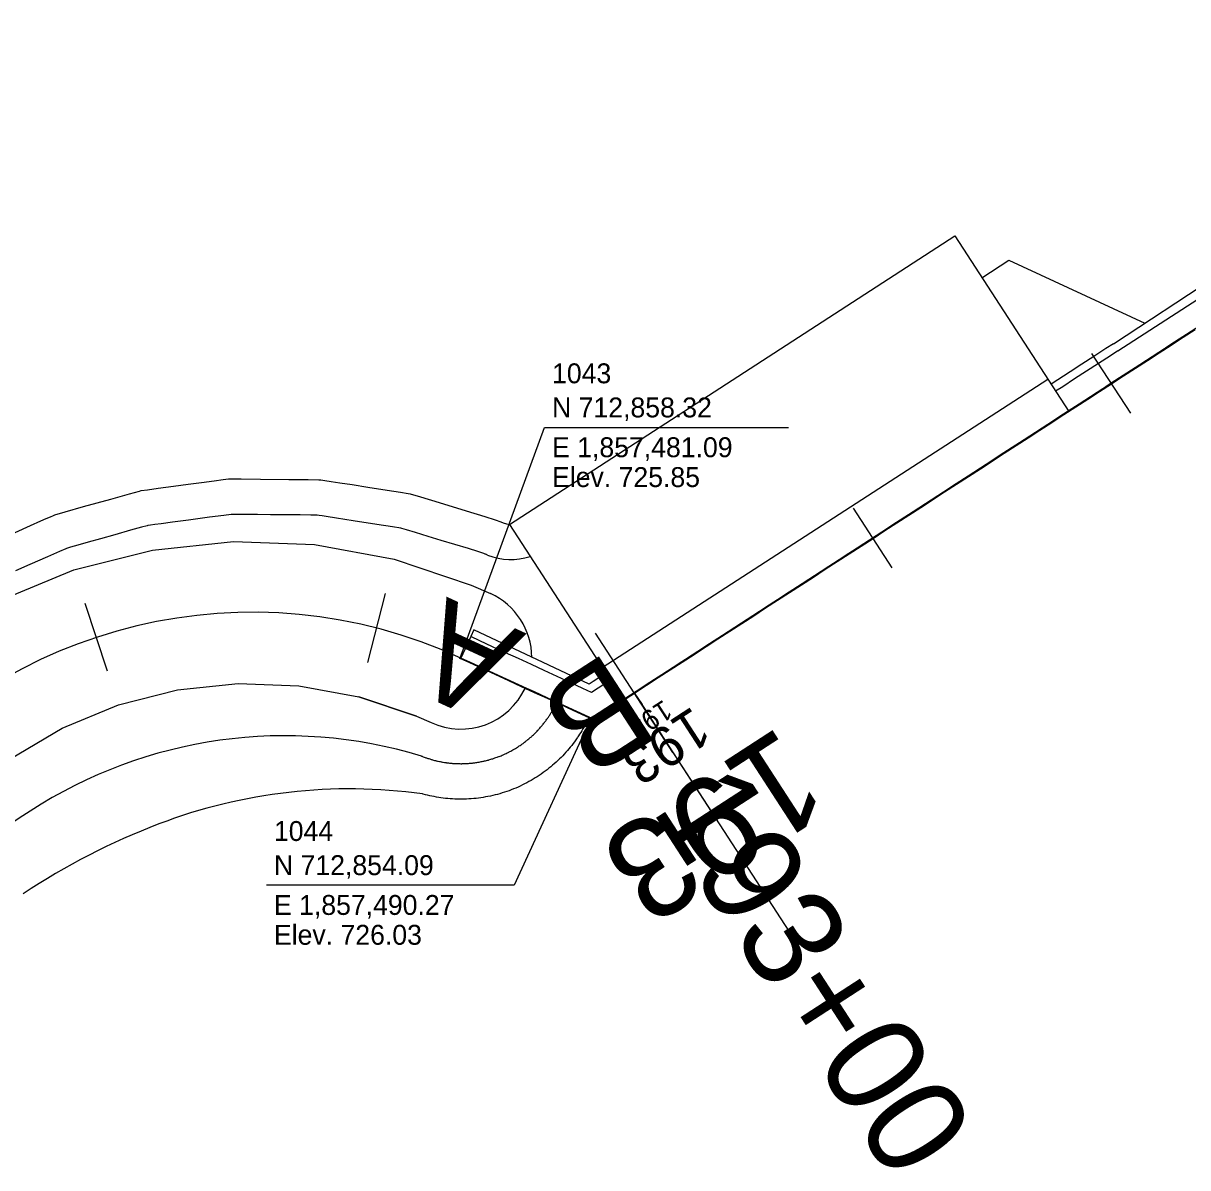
# Model space of a CAD drawing. Extents: x 1823824 to 1861612, y 706975 to 726130.
# Drawn here: x 1825981.6 to 1826063.6, y 712859.4 to 712939.9 of the extents above; entities that cross this region are included whole.
import ezdxf

# ---------------------------------------------------------------- set-up
doc = ezdxf.new("R2010")
doc.units = 0
for name, color, linetype in [('DR_X_Flood_Boundary', 7, 'Continuous'), ('GE_X_CL_10', 7, 'Continuous'), ('GE_X_CL_100', 7, 'Continuous'), ('GE_X_CL_20', 7, 'Continuous'), ('GE_X_CL_200', 7, 'Continuous'), ('GE_X_CL_50', 7, 'Continuous'), ('SC_Scratch1', 7, 'Continuous'), ('SC_Scratch2', 7, 'Continuous'), ('SC_Scratch5', 7, 'Continuous'), ('SC_Scratch6', 7, 'Continuous')]:
    doc.layers.add(name, color=color, linetype=linetype)

msp = doc.modelspace()

# ---------------------------------------------------------------- linework, layer by layer
at = {"layer": 'DR_X_Flood_Boundary'}
for p, q in [((1826097.226, 712939.908), (1826021.744, 712890.951)), ((1826021.744, 712890.951), (1826012.417, 712895.255))]:
    msp.add_line(p, q, dxfattribs=at)
msp.add_arc((1825997.753, 712863.475), 35, 65.23015, 141.66261, dxfattribs=at)
at = {"layer": 'GE_X_CL_10'}
msp.add_line((1826024.619, 712892.816), (1826025.163, 712891.977), dxfattribs=at)
at = {"layer": 'GE_X_CL_100'}
msp.add_line((1826024.619, 712892.816), (1826030.06, 712884.426), dxfattribs=at)
at = {"layer": 'GE_X_CL_20'}
msp.add_line((1826024.619, 712892.816), (1826025.707, 712891.138), dxfattribs=at)
at = {"layer": 'GE_X_CL_200'}
msp.add_line((1826024.619, 712892.816), (1826035.502, 712876.036), dxfattribs=at)
at = {"layer": 'GE_X_CL_50'}
msp.add_line((1826024.619, 712892.816), (1826027.34, 712888.621), dxfattribs=at)
at = {"layer": 'SC_Scratch1'}
for p, q in [((1826058.32, 712917.366), (1826076.72, 712929.427)), ((1826058.646, 712916.864), (1826077.104, 712928.835)), ((1826015.839, 712904.649), (1826047.173, 712924.947)), ((1826047.173, 712924.947), (1826055.18, 712912.602)), ((1826049.077, 712922.011), (1826050.965, 712923.234)), ((1826050.965, 712923.234), (1826060.534, 712918.82)), ((1826022.369, 712894.582), (1826053.703, 712914.88)), ((1826015.839, 712904.649), (1826023.856, 712892.289)), ((1826021.434, 712893.406), (1826013.329, 712897.23)), ((1826022.938, 712893.705), (1826021.608, 712892.842)), ((1826009.3, 712891.163), (1826005.241, 712892.525))]:
    msp.add_line(p, q, dxfattribs=at)
for points in [[(1826012.4, 712895.223), (1826012.402, 712895.222), (1826013.036, 712894.93), (1826013.944, 712894.512), (1826014.852, 712894.094), (1826015.761, 712893.675), (1826016.669, 712893.257), (1826017.578, 712892.84), (1826018.486, 712892.422), (1826019.395, 712892.003), (1826020.303, 712891.585), (1826021.211, 712891.167), (1826021.758, 712890.929), (1826022.115, 712891.161), (1826022.954, 712891.705), (1826023.794, 712892.249), (1826024.633, 712892.793), (1826025.471, 712893.338), (1826026.31, 712893.882), (1826027.149, 712894.426), (1826027.988, 712894.971), (1826028.827, 712895.515), (1826029.666, 712896.059), (1826030.505, 712896.603), (1826031.344, 712897.147), (1826032.183, 712897.691), (1826033.022, 712898.235), (1826033.861, 712898.779), (1826034.7, 712899.323), (1826035.539, 712899.867), (1826036.378, 712900.411), (1826037.218, 712900.955), (1826038.057, 712901.499), (1826038.896, 712902.043), (1826039.735, 712902.587), (1826040.574, 712903.131), (1826041.413, 712903.675), (1826042.252, 712904.219), (1826043.091, 712904.763), (1826043.93, 712905.307), (1826044.769, 712905.852), (1826045.608, 712906.396), (1826046.447, 712906.94), (1826047.286, 712907.484), (1826048.125, 712908.028), (1826048.964, 712908.572), (1826049.803, 712909.116), (1826050.642, 712909.66), (1826051.481, 712910.204), (1826052.321, 712910.748), (1826053.16, 712911.292), (1826053.999, 712911.836), (1826054.838, 712912.38), (1826055.677, 712912.924), (1826056.516, 712913.468), (1826057.355, 712914.012), (1826058.194, 712914.556), (1826059.033, 712915.1), (1826059.872, 712915.644), (1826060.711, 712916.188), (1826061.55, 712916.732), (1826062.389, 712917.276), (1826063.228, 712917.82), (1826064.067, 712918.365)], [(1826064.051, 712918.39), (1826063.212, 712917.846), (1826062.373, 712917.302), (1826061.534, 712916.758), (1826060.695, 712916.214), (1826059.856, 712915.67), (1826059.017, 712915.126), (1826058.178, 712914.581), (1826057.339, 712914.037), (1826056.5, 712913.493), (1826055.661, 712912.949), (1826054.822, 712912.405), (1826053.983, 712911.861), (1826053.144, 712911.316), (1826052.305, 712910.772), (1826051.466, 712910.228), (1826050.627, 712909.684), (1826049.788, 712909.14), (1826048.949, 712908.596), (1826048.11, 712908.052), (1826047.271, 712907.507), (1826046.432, 712906.963), (1826045.593, 712906.419), (1826044.754, 712905.875), (1826043.915, 712905.331), (1826043.076, 712904.787), (1826042.237, 712904.242), (1826041.398, 712903.698), (1826040.559, 712903.154), (1826039.72, 712902.61), (1826038.881, 712902.066), (1826038.042, 712901.522), (1826037.203, 712900.978), (1826036.364, 712900.433), (1826035.525, 712899.889), (1826034.686, 712899.345), (1826033.847, 712898.801), (1826033.008, 712898.257), (1826032.169, 712897.713), (1826031.33, 712897.168), (1826030.491, 712896.624), (1826029.652, 712896.08), (1826028.813, 712895.536), (1826027.974, 712894.992), (1826027.135, 712894.448), (1826026.296, 712893.904), (1826025.457, 712893.359), (1826024.618, 712892.815), (1826023.779, 712892.271), (1826022.94, 712891.727), (1826022.101, 712891.183), (1826021.744, 712890.951), (1826021.223, 712891.192), (1826020.315, 712891.611), (1826019.407, 712892.03), (1826018.499, 712892.448), (1826017.591, 712892.867), (1826016.683, 712893.286)], [(1826058.32, 712917.366), (1826057.787, 712917.021), (1826056.948, 712916.477), (1826056.11, 712915.931), (1826055.272, 712915.385), (1826053.938, 712914.516)], [(1826058.646, 712916.864), (1826058.113, 712916.518), (1826057.274, 712915.974), (1826056.435, 712915.43), (1826055.596, 712914.886), (1826054.757, 712914.342), (1826054.261, 712914.019)], [(1826012.348, 712895.188), (1826018.314, 712911.484), (1826035.478, 712911.484)], [(1826012.348, 712895.188), (1826018.314, 712911.484), (1826035.478, 712911.484)], [(1826013.329, 712897.23), (1826013.111, 712896.763), (1826012.415, 712895.256), (1826012.401, 712895.222)], [(1826017.378, 712894.794), (1826016.47, 712895.213), (1826015.562, 712895.632), (1826014.654, 712896.051), (1826013.746, 712896.47), (1826013.112, 712896.762), (1826013.111, 712896.763)], [(1826016.683, 712893.286), (1826015.775, 712893.705), (1826014.867, 712894.124), (1826013.959, 712894.543), (1826013.051, 712894.962), (1826012.417, 712895.255), (1826012.415, 712895.256)], [(1826021.608, 712892.842), (1826021.01, 712893.118), (1826020.102, 712893.537), (1826019.194, 712893.956), (1826018.286, 712894.375), (1826017.378, 712894.794)], [(1826022.627, 712894.184), (1826021.727, 712893.597), (1826021.434, 712893.406)], [(1826021.528, 712890.958), (1826016.167, 712879.287), (1825998.75, 712879.287)], [(1826021.528, 712890.958), (1826016.167, 712879.287), (1825998.75, 712879.287)]]:
    msp.add_lwpolyline(points, dxfattribs=at)
at = {"layer": 'SC_Scratch2'}
for p, q in [((1825988.339, 712891.96), (1825992.491, 712893.01)), ((1825992.491, 712893.01), (1825996.749, 712893.458)), ((1825996.749, 712893.458), (1826001.028, 712893.295)), ((1826001.028, 712893.295), (1826005.241, 712892.525)), ((1826005.241, 712892.525), (1826009.3, 712891.163)), ((1825984.38, 712890.329), (1825988.339, 712891.96)), ((1826009.3, 712891.163), (1826010.32, 712890.715)), ((1825980.693, 712888.152), (1825984.38, 712890.329))]:
    msp.add_line(p, q, dxfattribs=at)
for points in [[(1825981.062, 712904.097), (1825982.138, 712904.575), (1825982.869, 712904.9), (1825983.255, 712905.072), (1825983.55, 712905.2), (1825983.754, 712905.284), (1825983.866, 712905.325), (1825984.576, 712905.531), (1825985.883, 712905.904), (1825987.788, 712906.442), (1825989.099, 712906.809), (1825989.815, 712907.005), (1825989.936, 712907.03), (1825990.376, 712907.095), (1825991.134, 712907.199), (1825992.212, 712907.343), (1825993.226, 712907.479), (1825994.177, 712907.606), (1825995.065, 712907.724), (1825995.7, 712907.806), (1825996.081, 712907.851), (1825996.21, 712907.858), (1825996.957, 712907.857), (1825998.323, 712907.846), (1826000.308, 712907.826), (1826001.675, 712907.808), (1826002.426, 712907.794), (1826002.558, 712907.784), (1826002.851, 712907.745), (1826003.303, 712907.678), (1826003.916, 712907.584), (1826004.775, 712907.452)], [(1826004.775, 712907.452), (1826005.881, 712907.281), (1826007.234, 712907.073), (1826008.181, 712906.924), (1826008.721, 712906.834), (1826008.856, 712906.803), (1826009.58, 712906.589), (1826010.895, 712906.191), (1826012.8, 712905.61), (1826014.114, 712905.206), (1826014.837, 712904.978), (1826014.97, 712904.927), (1826015.079, 712904.885), (1826015.163, 712904.851), (1826015.224, 712904.826), (1826015.399, 712904.756), (1826015.64, 712904.687), (1826015.839, 712904.649)], [(1826008.264, 712904.376), (1826008.201, 712904.391), (1826007.611, 712904.485), (1826006.496, 712904.658), (1826004.854, 712904.911), (1826003.666, 712905.094), (1826002.934, 712905.207), (1826002.656, 712905.25), (1826002.451, 712905.28), (1826002.319, 712905.297), (1826002.258, 712905.302), (1826001.859, 712905.309), (1826001.12, 712905.318), (1826000.043, 712905.329), (1825999.037, 712905.339), (1825998.104, 712905.349), (1825997.243, 712905.358), (1825996.65, 712905.363), (1825996.326, 712905.363), (1825996.27, 712905.36), (1825995.742, 712905.292), (1825994.74, 712905.159), (1825993.265, 712904.962), (1825992.133, 712904.811), (1825991.345, 712904.706), (1825990.901, 712904.647), (1825990.588, 712904.604), (1825990.407, 712904.577), (1825990.357, 712904.567), (1825989.951, 712904.455), (1825989.189, 712904.241), (1825988.071, 712903.925), (1825987.078, 712903.644), (1825986.21, 712903.399), (1825985.468, 712903.189), (1825984.958, 712903.044), (1825984.681, 712902.964), (1825984.637, 712902.948), (1825984.193, 712902.753), (1825983.348, 712902.379), (1825982.103, 712901.825), (1825981.1, 712901.38)], [(1826014.304, 712902.503), (1826014.251, 712902.524), (1826014.221, 712902.536), (1826014.192, 712902.548), (1826014.162, 712902.56), (1826014.133, 712902.572), (1826014.092, 712902.588), (1826014.039, 712902.609), (1826013.974, 712902.634), (1826013.61, 712902.748), (1826012.947, 712902.952), (1826011.985, 712903.246), (1826011.044, 712903.533), (1826010.125, 712903.813), (1826009.226, 712904.088), (1826008.606, 712904.275), (1826008.264, 712904.376)], [(1825979.922, 712899.281), (1825985.202, 712901.455), (1825990.737, 712902.855), (1825996.415, 712903.452), (1826002.12, 712903.236), (1826007.736, 712902.209), (1826013.149, 712900.393), (1826014.51, 712899.796)], [(1826015.44, 712888.468), (1826015.48, 712888.486), (1826015.531, 712888.511), (1826015.595, 712888.541), (1826015.672, 712888.577), (1826015.735, 712888.608), (1826015.786, 712888.633), (1826015.825, 712888.654), (1826015.875, 712888.68), (1826015.938, 712888.714), (1826016.012, 712888.754), (1826016.073, 712888.788), (1826016.123, 712888.816), (1826016.16, 712888.838), (1826016.209, 712888.867), (1826016.269, 712888.903), (1826016.341, 712888.947), (1826016.4, 712888.984), (1826016.448, 712889.014), (1826016.484, 712889.038), (1826016.531, 712889.07), (1826016.589, 712889.109), (1826016.658, 712889.156), (1826016.715, 712889.195), (1826016.761, 712889.228), (1826016.795, 712889.253), (1826016.84, 712889.287), (1826016.896, 712889.329), (1826016.962, 712889.379), (1826017.017, 712889.421), (1826017.06, 712889.456), (1826017.093, 712889.483), (1826017.136, 712889.518), (1826017.189, 712889.562), (1826017.252, 712889.615), (1826017.304, 712889.66), (1826017.346, 712889.696), (1826017.377, 712889.724), (1826017.418, 712889.762), (1826017.468, 712889.808), (1826017.527, 712889.863), (1826017.577, 712889.91), (1826017.616, 712889.948), (1826017.646, 712889.978), (1826017.684, 712890.017), (1826017.731, 712890.065), (1826017.787, 712890.122), (1826017.834, 712890.171), (1826017.871, 712890.21), (1826017.899, 712890.241), (1826017.935, 712890.281), (1826017.979, 712890.331), (1826018.032, 712890.391), (1826018.075, 712890.441), (1826018.11, 712890.482), (1826018.136, 712890.513), (1826018.169, 712890.555), (1826018.211, 712890.606), (1826018.26, 712890.667), (1826018.3, 712890.719), (1826018.333, 712890.761), (1826018.357, 712890.793), (1826018.388, 712890.835), (1826018.426, 712890.888), (1826018.471, 712890.95), (1826018.511, 712891.006), (1826018.545, 712891.055), (1826018.574, 712891.098), (1826018.604, 712891.144), (1826018.638, 712891.194), (1826018.673, 712891.248), (1826018.703, 712891.296), (1826018.729, 712891.336), (1826018.749, 712891.369), (1826018.775, 712891.413), (1826018.807, 712891.467), (1826018.845, 712891.532), (1826018.877, 712891.586), (1826018.902, 712891.63), (1826018.92, 712891.664), (1826018.944, 712891.708), (1826018.973, 712891.763), (1826019.008, 712891.828), (1826019.037, 712891.882), (1826019.059, 712891.927), (1826019.076, 712891.961), (1826019.097, 712892.005), (1826019.123, 712892.06), (1826019.155, 712892.126), (1826019.163, 712892.142)], [(1826021.431, 712891.096), (1826021.415, 712891.062), (1826021.352, 712890.928), (1826021.286, 712890.796), (1826021.219, 712890.663), (1826021.148, 712890.531), (1826021.076, 712890.399), (1826021.001, 712890.268), (1826020.923, 712890.137), (1826020.848, 712890.013), (1826020.774, 712889.896), (1826020.702, 712889.786), (1826020.65, 712889.706), (1826020.617, 712889.656), (1826020.604, 712889.637), (1826020.565, 712889.582), (1826020.5, 712889.491), (1826020.407, 712889.364), (1826020.313, 712889.238), (1826020.216, 712889.113), (1826020.117, 712888.989), (1826020.015, 712888.866), (1826019.911, 712888.744), (1826019.804, 712888.623), (1826019.695, 712888.504), (1826019.584, 712888.386), (1826019.47, 712888.269), (1826019.354, 712888.154), (1826019.235, 712888.04), (1826019.115, 712887.928), (1826018.992, 712887.818), (1826018.867, 712887.709), (1826018.739, 712887.602), (1826018.61, 712887.497), (1826018.479, 712887.394), (1826018.345, 712887.292), (1826018.209, 712887.193), (1826018.072, 712887.096), (1826017.932, 712887.001), (1826017.791, 712886.908), (1826017.648, 712886.818), (1826017.503, 712886.73), (1826017.356, 712886.644), (1826017.208, 712886.561), (1826017.058, 712886.479), (1826016.906, 712886.401), (1826016.753, 712886.325), (1826016.599, 712886.252), (1826016.443, 712886.181), (1826016.286, 712886.113), (1826016.128, 712886.047), (1826015.968, 712885.985), (1826015.808, 712885.925), (1826015.646, 712885.868), (1826015.484, 712885.813), (1826015.321, 712885.762), (1826015.156, 712885.713), (1826014.992, 712885.667), (1826014.826, 712885.625), (1826014.66, 712885.584), (1826014.494, 712885.547), (1826014.327, 712885.513), (1826014.16, 712885.482), (1826013.992, 712885.453), (1826013.825, 712885.428), (1826013.657, 712885.405), (1826013.489, 712885.385), (1826013.322, 712885.369), (1826013.154, 712885.355), (1826012.986, 712885.344), (1826012.819, 712885.335), (1826012.652, 712885.33), (1826012.486, 712885.327), (1826012.32, 712885.327), (1826012.154, 712885.33), (1826011.99, 712885.336), (1826011.825, 712885.344), (1826011.662, 712885.356), (1826011.499, 712885.369), (1826011.337, 712885.386), (1826011.177, 712885.404), (1826011.017, 712885.426), (1826010.858, 712885.45), (1826010.7, 712885.476), (1826010.543, 712885.505), (1826010.387, 712885.536), (1826010.233, 712885.569)], [(1826009.648, 712888.359), (1826009.693, 712888.341), (1826009.728, 712888.327), (1826009.775, 712888.31), (1826009.834, 712888.288), (1826009.904, 712888.262), (1826009.963, 712888.241), (1826010.011, 712888.224), (1826010.048, 712888.212), (1826010.096, 712888.196), (1826010.157, 712888.177), (1826010.229, 712888.154), (1826010.289, 712888.135), (1826010.339, 712888.12), (1826010.377, 712888.11), (1826010.427, 712888.096), (1826010.489, 712888.079), (1826010.563, 712888.059), (1826010.626, 712888.043), (1826010.677, 712888.031), (1826010.716, 712888.022), (1826010.767, 712888.01), (1826010.831, 712887.996), (1826010.907, 712887.98), (1826010.972, 712887.966), (1826011.024, 712887.956), (1826011.064, 712887.949), (1826011.116, 712887.94), (1826011.182, 712887.929), (1826011.26, 712887.916), (1826011.325, 712887.905), (1826011.378, 712887.897), (1826011.419, 712887.892), (1826011.473, 712887.885), (1826011.539, 712887.877), (1826011.619, 712887.868), (1826011.686, 712887.861), (1826011.74, 712887.855), (1826011.781, 712887.852), (1826011.836, 712887.848), (1826011.904, 712887.843), (1826011.984, 712887.838), (1826012.052, 712887.834), (1826012.107, 712887.831), (1826012.149, 712887.83), (1826012.204, 712887.828), (1826012.273, 712887.827), (1826012.354, 712887.826), (1826012.423, 712887.825), (1826012.479, 712887.825), (1826012.521, 712887.826), (1826012.577, 712887.827), (1826012.646, 712887.829), (1826012.728, 712887.832), (1826012.797, 712887.835), (1826012.853, 712887.838), (1826012.896, 712887.841), (1826012.952, 712887.845), (1826013.021, 712887.85), (1826013.104, 712887.857), (1826013.174, 712887.864), (1826013.23, 712887.869), (1826013.273, 712887.875), (1826013.329, 712887.882), (1826013.398, 712887.891), (1826013.481, 712887.902), (1826013.55, 712887.912), (1826013.606, 712887.921), (1826013.649, 712887.928), (1826013.705, 712887.938), (1826013.774, 712887.951), (1826013.857, 712887.967), (1826013.926, 712887.98), (1826013.982, 712887.992), (1826014.024, 712888.001), (1826014.08, 712888.014), (1826014.148, 712888.031), (1826014.23, 712888.051), (1826014.299, 712888.068), (1826014.354, 712888.082), (1826014.396, 712888.094), (1826014.451, 712888.11), (1826014.519, 712888.13), (1826014.6, 712888.154), (1826014.668, 712888.175), (1826014.722, 712888.192), (1826014.764, 712888.206), (1826014.818, 712888.225), (1826014.885, 712888.248), (1826014.965, 712888.276), (1826015.031, 712888.301), (1826015.085, 712888.321), (1826015.125, 712888.337), (1826015.179, 712888.359), (1826015.244, 712888.385), (1826015.322, 712888.418), (1826015.387, 712888.445), (1826015.44, 712888.468)], [(1826010.233, 712885.569), (1826010.08, 712885.605), (1826009.928, 712885.643), (1826009.778, 712885.683), (1826009.721, 712885.699)]]:
    msp.add_lwpolyline(points, dxfattribs=at)
for centre, radius, start, end in [((1826015.931, 712906.57), 4.38, 248.19859, 288.12023), ((1826012.415, 712895.256), 5, 0.53053, 65.22886), ((1826012.415, 712895.256), 5, 245.23419, 335.22793), ((1826000.046, 712856.794), 32.994, 73.07296, 122.91214), ((1826004.584, 712848.357), 37.694, 82.16553, 110.8476), ((1826027.552, 712814.295), 83.617, 122.91214, 143.04552), ((1826008.207, 712838.843), 47.875, 110.8476, 123.71112)]:
    msp.add_arc(centre, radius, start, end, dxfattribs=at)
at = {"layer": 'SC_Scratch5'}
for points in [[(1826059.539, 712912.485), (1826056.818, 712916.679)], [(1826042.759, 712901.601), (1826040.038, 712905.796)], [(1826005.865, 712894.947), (1826007.113, 712899.788)], [(1825987.556, 712894.334), (1825985.987, 712899.081)], [(1826027.34, 712888.621), (1826021.898, 712897.011)]]:
    msp.add_lwpolyline(points, dxfattribs=at)

# ---------------------------------------------------------------- texts
at = {"layer": 'GE_X_CL_10'}
msp.add_text('193', height=1.4, rotation=212.96689, dxfattribs=at).set_placement((1826026.683, 712892.367))
at = {"layer": 'GE_X_CL_20'}
msp.add_text('193', height=2.8, rotation=212.96689, dxfattribs=at).set_placement((1826028.748, 712891.918))
at = {"layer": 'GE_X_CL_50'}
msp.add_text('193', height=7, rotation=212.96689, dxfattribs=at).set_placement((1826034.941, 712890.571))
at = {"layer": 'SC_Scratch1'}
for s, p in [(' 1043', (1826018.314, 712914.584)), (' 1043', (1826018.314, 712914.584)), (' N 712,858.32', (1826018.314, 712912.184)), (' N 712,858.32', (1826018.314, 712912.184)), (' E 1,857,481.09', (1826018.314, 712909.384)), (' E 1,857,481.09', (1826018.314, 712909.384)), (' Elev. 725.85 ', (1826018.314, 712907.284)), (' Elev. 725.85 ', (1826018.314, 712907.284)), (' 1044', (1825998.75, 712882.386)), (' 1044', (1825998.75, 712882.386)), (' N 712,854.09', (1825998.75, 712879.986)), (' N 712,854.09', (1825998.75, 712879.986)), (' E 1,857,490.27', (1825998.75, 712877.186)), (' E 1,857,490.27', (1825998.75, 712877.186)), (' Elev. 726.03 ', (1825998.75, 712875.086)), (' Elev. 726.03 ', (1825998.75, 712875.086))]:
    msp.add_text(s, height=1.4, dxfattribs=at).set_placement(p)
at = {"layer": 'SC_Scratch5'}
msp.add_text('193+00', height=7, rotation=302.96689, dxfattribs=at).set_placement((1826025.764, 712884.619))
at = {"layer": 'SC_Scratch6'}
for s, rotation, p in [('A', 155.23015, (1826017.061, 712896.966)), ('B', 212.96689, (1826022.776, 712895.792))]:
    msp.add_text(s, height=7, rotation=rotation, dxfattribs=at).set_placement(p)

doc.saveas('drawing.dxf')
